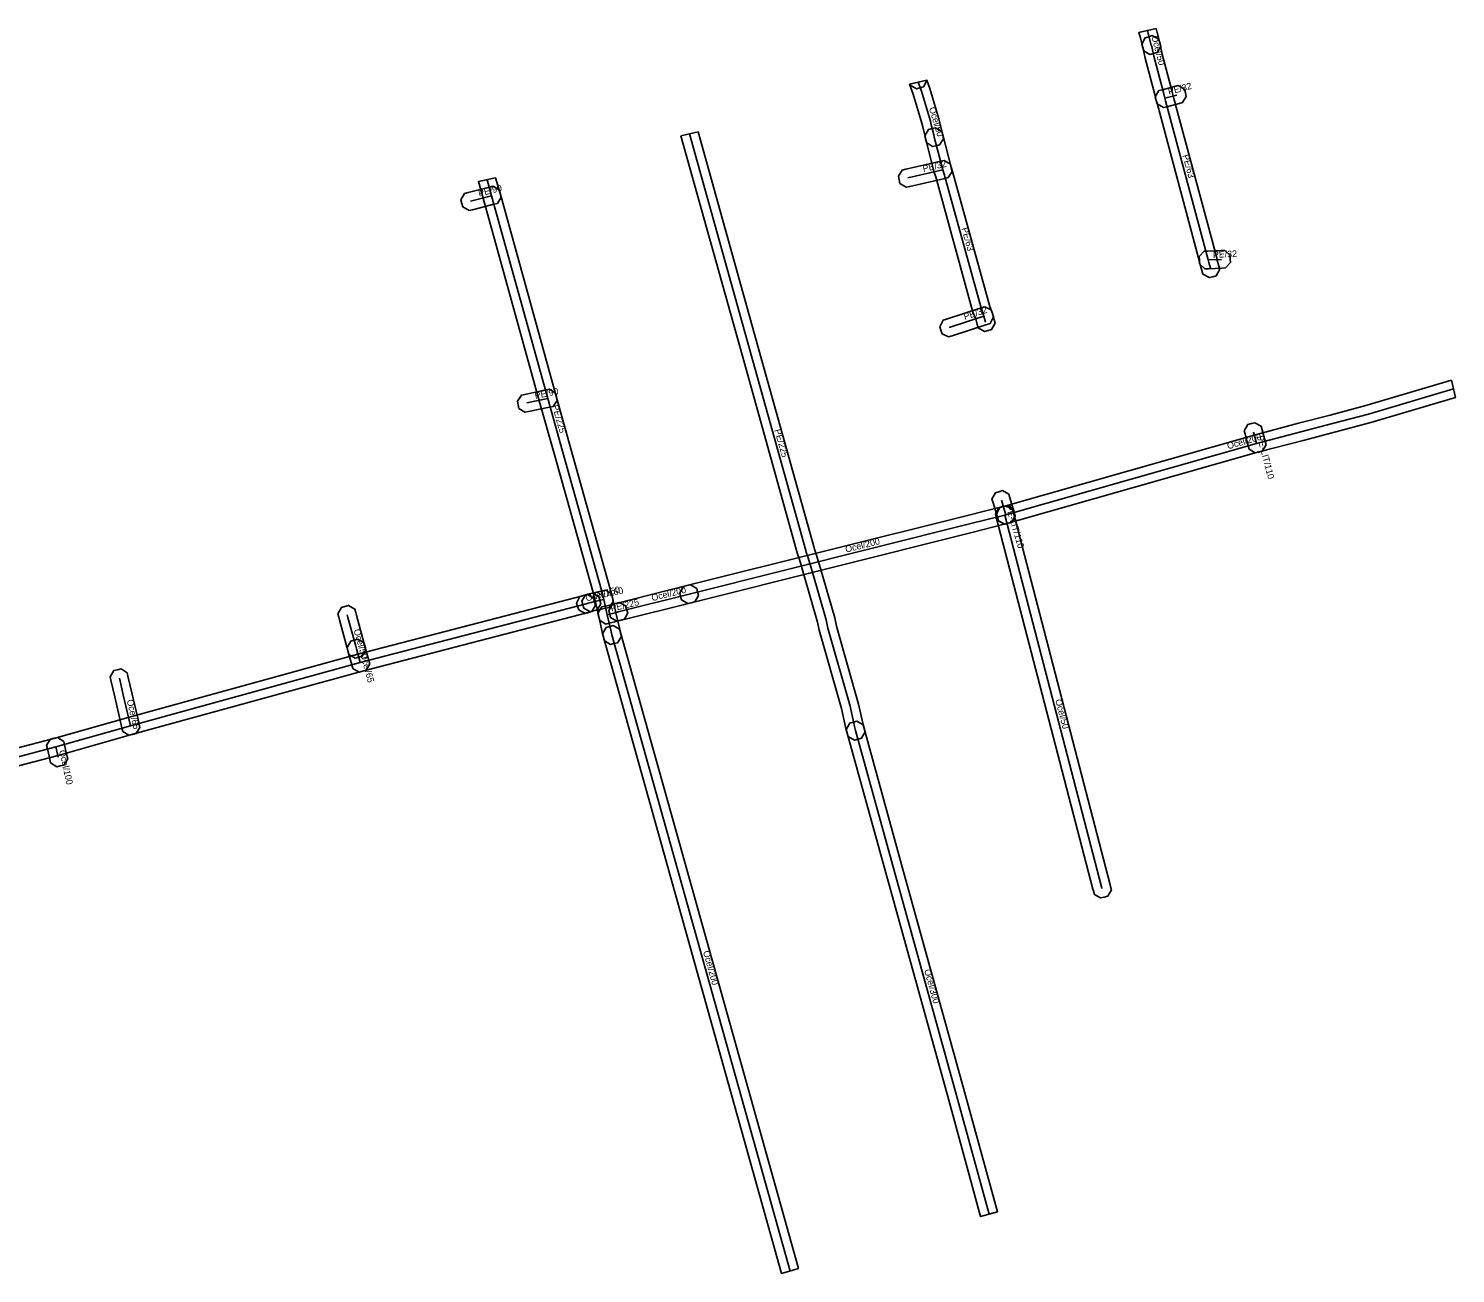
# Model space of a CAD drawing. Extents: x -599265 to -598944, y -1158962 to -1158820.
# Drawn here: x -599106.1 to -598943.9, y -1158961.6 to -1158820.1 of the extents above; entities that cross this region are included whole.
import ezdxf

# ---------------------------------------------------------------- set-up
doc = ezdxf.new("R2010")
doc.units = 0
for name, color, linetype in [('1', 7, 'Continuous'), ('14', 7, 'Continuous'), ('20', 7, 'Continuous'), ('24', 7, 'Continuous'), ('30', 7, 'Continuous')]:
    doc.layers.add(name, color=color, linetype=linetype)

msp = doc.modelspace()

# ---------------------------------------------------------------- linework, layer by layer
at = {"layer": '1'}
for points in [[(-598979.77, -1158821.02), (-598979.92, -1158820.5), (-598977.96, -1158820.06), (-598977.84, -1158820.51), (-598977.53, -1158821.69), (-598977.43, -1158822.09), (-598977.85, -1158822.8), (-598978.25, -1158822.91), (-598978.65, -1158823.01), (-598979.36, -1158822.59), (-598979.47, -1158822.19)], [(-598977.67, -1158821.25), (-598977.54, -1158821.65), (-598977.48, -1158821.86), (-598977.26, -1158822.98), (-598976.15, -1158827.11), (-598976.01, -1158827.73), (-598975.93, -1158828.01), (-598971.07, -1158846.13), (-598971.01, -1158846.42), (-598970.83, -1158847.05), (-598970.72, -1158847.44), (-598971.12, -1158848.17), (-598971.52, -1158848.28), (-598971.92, -1158848.39), (-598972.64, -1158847.99), (-598972.75, -1158847.59), (-598972.95, -1158846.9), (-598973.01, -1158846.6), (-598977.85, -1158828.55), (-598977.95, -1158828.24), (-598978.09, -1158827.58), (-598979.21, -1158823.43), (-598979.42, -1158822.35), (-598979.45, -1158822.24), (-598979.58, -1158821.84), (-598979.19, -1158821.11), (-598978.8, -1158820.99), (-598978.4, -1158820.86)], [(-599005.97, -1158826.4), (-599005.97, -1158826.39), (-599004.01, -1158825.95), (-599003.67, -1158826.89), (-599002.64, -1158830.33), (-599002.54, -1158830.79), (-599002.27, -1158831.9), (-599002.2, -1158832.2), (-599002.12, -1158832.61), (-599002.57, -1158833.3), (-599002.97, -1158833.39), (-599003.38, -1158833.47), (-599004.07, -1158833.02), (-599004.16, -1158832.62), (-599004.21, -1158832.35), (-599004.49, -1158831.24), (-599004.58, -1158830.83), (-599005.57, -1158827.51)], [(-599005.92, -1158826.5), (-599005.95, -1158826.39), (-599004, -1158825.94), (-599004, -1158825.96), (-599004.4, -1158826.68), (-599004.8, -1158826.8), (-599005.2, -1158826.91)], [(-598977.64, -1158827.12), (-598977.23, -1158827.02), (-598975.85, -1158826.65), (-598975.45, -1158826.55), (-598974.73, -1158826.96), (-598974.63, -1158827.36), (-598974.53, -1158827.77), (-598974.94, -1158828.48), (-598975.34, -1158828.59), (-598976.73, -1158828.95), (-598977.13, -1158829.05), (-598977.84, -1158828.64), (-598977.95, -1158828.24), (-598978.05, -1158827.84)], [(-599031.97, -1158832.27), (-599030.02, -1158831.82), (-599022.84, -1158857.56), (-599016.83, -1158879.12), (-599016.78, -1158879.28), (-599016.6, -1158879.85), (-599016.1, -1158881.47), (-599014.49, -1158887.07), (-599014.3, -1158888.01), (-599011.78, -1158896.89), (-599011.27, -1158899.19), (-599011.15, -1158899.63), (-599011.04, -1158900.03), (-599011.44, -1158900.75), (-599011.84, -1158900.86), (-599012.24, -1158900.97), (-599012.96, -1158900.57), (-599013.07, -1158900.17), (-599013.21, -1158899.67), (-599013.72, -1158897.38), (-599016.24, -1158888.49), (-599016.43, -1158887.55), (-599018.02, -1158882.05), (-599018.51, -1158880.45), (-599018.68, -1158879.9), (-599018.75, -1158879.7), (-599024.76, -1158858.1)], [(-599002.32, -1158831.76), (-599002.21, -1158832.16), (-599001.26, -1158835.83), (-599001.09, -1158836.3), (-598996.87, -1158851.67), (-598996.57, -1158852.45), (-598996.36, -1158853.17), (-598996.25, -1158853.57), (-598996.66, -1158854.29), (-598997.06, -1158854.41), (-598997.45, -1158854.52), (-598998.18, -1158854.11), (-598998.29, -1158853.71), (-598998.46, -1158853.09), (-598998.77, -1158852.3), (-599002.99, -1158836.91), (-599003.17, -1158836.43), (-599004.15, -1158832.66), (-599004.25, -1158832.26), (-599003.83, -1158831.54), (-599003.43, -1158831.44), (-599003.03, -1158831.34)], [(-599001.59, -1158837.01), (-599001.99, -1158837.1), (-599005.96, -1158838.01), (-599006.36, -1158838.11), (-599007.07, -1158837.67), (-599007.16, -1158837.26), (-599007.25, -1158836.86), (-599006.81, -1158836.16), (-599006.41, -1158836.06), (-599002.44, -1158835.15), (-599002.03, -1158835.06), (-599001.33, -1158835.5), (-599001.24, -1158835.91), (-599001.15, -1158836.31)], [(-599054.45, -1158839.34), (-599054.99, -1158837.47), (-599053.04, -1158837.03), (-599052.53, -1158838.8), (-599046.15, -1158861.87), (-599044.47, -1158867.86), (-599040.04, -1158883.68), (-599039.75, -1158884.76), (-599039.36, -1158886.5), (-599038.93, -1158888.39), (-599038.83, -1158888.8), (-599038.74, -1158889.2), (-599039.18, -1158889.9), (-599039.59, -1158890), (-599039.99, -1158890.09), (-599040.69, -1158889.65), (-599040.79, -1158889.24), (-599040.88, -1158888.84), (-599041.32, -1158886.94), (-599041.69, -1158885.24), (-599041.96, -1158884.2), (-599046.39, -1158868.4), (-599048.07, -1158862.41)], [(-599052.84, -1158839.94), (-599053.24, -1158840.04), (-599055.66, -1158840.66), (-599056.06, -1158840.76), (-599056.78, -1158840.34), (-599056.88, -1158839.94), (-599056.98, -1158839.54), (-599056.56, -1158838.82), (-599056.16, -1158838.72), (-599053.74, -1158838.1), (-599053.34, -1158838), (-599052.62, -1158838.42), (-599052.52, -1158838.82), (-599052.42, -1158839.22)], [(-598972.49, -1158845.39), (-598972.08, -1158845.37), (-598970.57, -1158845.31), (-598970.15, -1158845.29), (-598969.55, -1158845.86), (-598969.53, -1158846.27), (-598969.51, -1158846.68), (-598970.08, -1158847.29), (-598970.49, -1158847.31), (-598972, -1158847.37), (-598972.42, -1158847.38), (-598973.02, -1158846.82), (-598973.04, -1158846.41), (-598973.06, -1158845.99)], [(-598996.81, -1158853.59), (-598997.21, -1158853.72), (-599001.15, -1158855.01), (-599001.55, -1158855.13), (-599002.29, -1158854.76), (-599002.41, -1158854.36), (-599002.54, -1158853.97), (-599002.17, -1158853.23), (-599001.77, -1158853.1), (-598997.83, -1158851.82), (-598997.43, -1158851.69), (-598996.69, -1158852.06), (-598996.57, -1158852.46), (-598996.44, -1158852.85)], [(-598944.39, -1158860.06), (-598943.93, -1158862.01), (-598953.56, -1158864.86), (-598957.67, -1158865.95), (-598961.24, -1158866.89), (-598966.27, -1158868.21), (-598994.77, -1158876.32), (-598995.16, -1158876.44), (-598995.89, -1158876.03), (-598996, -1158875.63), (-598996.11, -1158875.24), (-598995.71, -1158874.51), (-598995.31, -1158874.4), (-598966.8, -1158866.29), (-598961.76, -1158864.95), (-598958.18, -1158864.01), (-598954.1, -1158862.94)], [(-599046.5, -1158863.03), (-599046.91, -1158863.12), (-599049.3, -1158863.62), (-599049.7, -1158863.7), (-599050.39, -1158863.25), (-599050.48, -1158862.84), (-599050.56, -1158862.44), (-599050.11, -1158861.75), (-599049.7, -1158861.66), (-599047.32, -1158861.16), (-599046.91, -1158861.08), (-599046.22, -1158861.53), (-599046.13, -1158861.94), (-599046.05, -1158862.34)], [(-598966.01, -1158865.29), (-598965.9, -1158865.69), (-598965.56, -1158867), (-598965.46, -1158867.4), (-598965.88, -1158868.11), (-598966.28, -1158868.22), (-598966.68, -1158868.32), (-598967.39, -1158867.9), (-598967.5, -1158867.5), (-598967.84, -1158866.2), (-598967.94, -1158865.8), (-598967.53, -1158865.08), (-598967.12, -1158864.98), (-598966.72, -1158864.88)], [(-598994.69, -1158873.01), (-598994.58, -1158873.41), (-598994.08, -1158875.08), (-598993.96, -1158875.47), (-598994.36, -1158876.2), (-598994.76, -1158876.32), (-598995.15, -1158876.44), (-598995.88, -1158876.04), (-598996, -1158875.64), (-598996.49, -1158873.98), (-598996.61, -1158873.58), (-598996.22, -1158872.85), (-598995.82, -1158872.73), (-598995.42, -1158872.61)], [(-599031.69, -1158883.51), (-599031.29, -1158883.41), (-598999.4, -1158875.43), (-598995.52, -1158874.45), (-598995.39, -1158874.42), (-598995.3, -1158874.4), (-598994.9, -1158874.29), (-598994.18, -1158874.7), (-598994.08, -1158875.1), (-598993.97, -1158875.5), (-598994.38, -1158876.22), (-598994.78, -1158876.32), (-598994.91, -1158876.36), (-598995.06, -1158876.39), (-598998.92, -1158877.37), (-599030.8, -1158885.35), (-599031.2, -1158885.45), (-599031.91, -1158885.03), (-599032.01, -1158884.63), (-599032.11, -1158884.22)], [(-598994.29, -1158874.74), (-598994.18, -1158875.14), (-598983.19, -1158917.42), (-598983.14, -1158917.61), (-598983.04, -1158918.01), (-598983.45, -1158918.72), (-598983.86, -1158918.83), (-598984.26, -1158918.93), (-598984.97, -1158918.52), (-598985.08, -1158918.11), (-598985.13, -1158917.92), (-598996.12, -1158875.64), (-598996.22, -1158875.24), (-598995.8, -1158874.53), (-598995.4, -1158874.42), (-598995, -1158874.32)], [(-599041.5, -1158886.18), (-599041.9, -1158886.29), (-599042.22, -1158886.37), (-599042.47, -1158886.45), (-599042.86, -1158886.57), (-599043.59, -1158886.18), (-599043.72, -1158885.78), (-599043.84, -1158885.39), (-599043.45, -1158884.66), (-599043.05, -1158884.53), (-599042.78, -1158884.45), (-599042.42, -1158884.35), (-599042.02, -1158884.25), (-599041.3, -1158884.66), (-599041.19, -1158885.06), (-599041.09, -1158885.47)], [(-599040.11, -1158885.9), (-599040.52, -1158885.98), (-599041.56, -1158886.19), (-599041.9, -1158886.28), (-599042.3, -1158886.39), (-599043.02, -1158885.98), (-599043.12, -1158885.58), (-599043.23, -1158885.18), (-599042.82, -1158884.46), (-599042.42, -1158884.35), (-599042.02, -1158884.25), (-599040.92, -1158884.02), (-599040.52, -1158883.94), (-599039.82, -1158884.39), (-599039.74, -1158884.8), (-599039.66, -1158885.21)], [(-599039.74, -1158885.53), (-599039.34, -1158885.43), (-599031.29, -1158883.41), (-599030.89, -1158883.31), (-599030.18, -1158883.74), (-599030.07, -1158884.14), (-599029.97, -1158884.54), (-599030.4, -1158885.25), (-599030.8, -1158885.35), (-599038.86, -1158887.37), (-599039.26, -1158887.47), (-599039.97, -1158887.04), (-599040.07, -1158886.64), (-599040.17, -1158886.24)], [(-599069.71, -1158891.24), (-599069.82, -1158890.84), (-599069.9, -1158890.54), (-599070.79, -1158887.3), (-599070.87, -1158887), (-599070.97, -1158886.6), (-599070.56, -1158885.88), (-599070.16, -1158885.77), (-599069.76, -1158885.67), (-599069.04, -1158886.08), (-599068.93, -1158886.48), (-599068.85, -1158886.78), (-599067.96, -1158890.02), (-599067.88, -1158890.32), (-599067.78, -1158890.72), (-599068.19, -1158891.44), (-599068.59, -1158891.55), (-599068.99, -1158891.65)], [(-599040.97, -1158885.84), (-599040.57, -1158885.75), (-599039.71, -1158885.55), (-599039.41, -1158885.45), (-599039.01, -1158885.32), (-599038.28, -1158885.7), (-599038.15, -1158886.09), (-599038.02, -1158886.49), (-599038.4, -1158887.22), (-599038.79, -1158887.35), (-599039.17, -1158887.47), (-599040.11, -1158887.69), (-599040.52, -1158887.79), (-599041.22, -1158887.35), (-599041.31, -1158886.95), (-599041.41, -1158886.54)], [(-599018.6, -1158961.08), (-599020.53, -1158961.63), (-599040.77, -1158889.29), (-599040.89, -1158888.89), (-599040.48, -1158888.17), (-599040.08, -1158888.06), (-599039.68, -1158887.95), (-599038.96, -1158888.35), (-599038.85, -1158888.75)], [(-599069.28, -1158892.83), (-599069.39, -1158892.43), (-599069.82, -1158890.84), (-599069.92, -1158890.44), (-599069.51, -1158889.72), (-599069.11, -1158889.61), (-599068.71, -1158889.51), (-599067.99, -1158889.92), (-599067.89, -1158890.32), (-599067.45, -1158891.91), (-599067.35, -1158892.31), (-599067.76, -1158893.03), (-599068.16, -1158893.14), (-599068.56, -1158893.24)], [(-599095.42, -1158899.99), (-599095.51, -1158899.59), (-599096.33, -1158896.06), (-599096.77, -1158894.18), (-599096.87, -1158893.78), (-599096.43, -1158893.07), (-599096.03, -1158892.98), (-599095.62, -1158892.88), (-599094.92, -1158893.32), (-599094.83, -1158893.72), (-599094.39, -1158895.6), (-599093.57, -1158899.13), (-599093.47, -1158899.54), (-599093.91, -1158900.24), (-599094.31, -1158900.33), (-599094.72, -1158900.43)], [(-598999.72, -1158940.98), (-598995.99, -1158954.61), (-598997.91, -1158955.16), (-599001.64, -1158941.51), (-599008.69, -1158916.08), (-599013.07, -1158900.17), (-599013.18, -1158899.77), (-599012.78, -1158899.05), (-599012.38, -1158898.94), (-599011.98, -1158898.83), (-599011.26, -1158899.24), (-599011.15, -1158899.64), (-599006.77, -1158915.54)], [(-599102.12, -1158901.13), (-599102.03, -1158901.53), (-599101.77, -1158902.71), (-599101.68, -1158903.12), (-599102.12, -1158903.82), (-599102.53, -1158903.91), (-599102.93, -1158904), (-599103.63, -1158903.55), (-599103.72, -1158903.15), (-599103.99, -1158901.97), (-599104.08, -1158901.56), (-599103.63, -1158900.86), (-599103.23, -1158900.77), (-599102.82, -1158900.68)]]:
    msp.add_lwpolyline(points, close=True, dxfattribs=at)
msp.add_lwpolyline([(-599109.54, -1158902.43), (-599103.27, -1158900.78), (-599094.81, -1158898.4), (-599068.68, -1158891.2), (-599043.01, -1158884.52), (-599042.61, -1158884.42), (-599041.9, -1158884.84), (-599041.79, -1158885.24), (-599041.69, -1158885.64), (-599042.11, -1158886.35), (-599042.51, -1158886.46), (-599068.16, -1158893.14), (-599094.27, -1158900.32), (-599102.75, -1158902.72), (-599109.03, -1158904.37)], dxfattribs=at)
at = {"layer": '14'}
for points in [[(-599054.01, -1158837.25), (-599053.49, -1158839.07), (-599047.11, -1158862.14), (-599045.43, -1158868.13), (-599041, -1158883.94), (-599040.72, -1158885), (-599040.34, -1158886.72), (-599039.9, -1158888.61), (-599039.81, -1158889.02)], [(-599053.49, -1158839.07), (-599055.91, -1158839.69)], [(-598995.04, -1158875.36), (-598966.53, -1158867.25), (-598961.5, -1158865.92), (-598957.92, -1158864.98), (-598953.83, -1158863.9), (-598944.16, -1158861.03)], [(-599047.11, -1158862.14), (-599049.5, -1158862.64)], [(-598966.87, -1158865.95), (-598966.53, -1158867.25)], [(-598995.54, -1158873.69), (-598995.04, -1158875.36)], [(-599031.04, -1158884.38), (-598999.16, -1158876.4), (-598995.29, -1158875.42), (-598995.15, -1158875.39), (-598995.04, -1158875.36)], [(-598995.15, -1158875.39), (-598984.16, -1158917.67), (-598984.11, -1158917.86)], [(-599039.1, -1158886.4), (-599031.04, -1158884.38)], [(-599042.76, -1158885.49), (-599068.42, -1158892.17), (-599094.54, -1158899.36), (-599103.01, -1158901.75), (-599109.28, -1158903.4), (-599121.29, -1158906.57), (-599128.03, -1158908.44), (-599139.52, -1158911.69), (-599140.38, -1158911.93), (-599166.16, -1158919.18), (-599194.33, -1158927.1), (-599199.24, -1158928.46), (-599225.65, -1158935.9)], [(-599042.16, -1158885.32), (-599042.5, -1158885.41), (-599042.76, -1158885.49)], [(-599040.72, -1158885), (-599041.79, -1158885.22), (-599042.16, -1158885.32)], [(-599068.85, -1158890.58), (-599068.93, -1158890.28), (-599069.82, -1158887.04), (-599069.9, -1158886.74)], [(-599040.34, -1158886.72), (-599039.44, -1158886.51), (-599039.1, -1158886.4)], [(-599039.81, -1158889.02), (-599019.56, -1158961.35)], [(-599068.42, -1158892.17), (-599068.85, -1158890.58)], [(-599094.54, -1158899.36), (-599095.36, -1158895.83), (-599095.8, -1158893.95)], [(-599103.01, -1158901.75), (-599102.75, -1158902.93)]]:
    msp.add_lwpolyline(points, dxfattribs=at)
at = {"layer": '24'}
for points in [[(-598978.94, -1158820.28), (-598978.81, -1158820.76), (-598978.5, -1158821.94)], [(-598978.5, -1158821.94), (-598978.45, -1158822.11), (-598978.23, -1158823.21), (-598977.12, -1158827.34), (-598976.98, -1158827.98), (-598976.89, -1158828.28), (-598972.04, -1158846.37), (-598971.98, -1158846.66), (-598971.79, -1158847.32)], [(-599004.99, -1158826.17), (-599004.62, -1158827.2), (-599003.61, -1158830.58), (-599003.52, -1158831.02), (-599003.24, -1158832.13), (-599003.18, -1158832.41)], [(-598976.98, -1158827.98), (-598975.6, -1158827.62)], [(-599012.11, -1158899.9), (-599012.24, -1158899.43), (-599012.75, -1158897.13), (-599015.27, -1158888.25), (-599015.46, -1158887.31), (-599017.06, -1158881.76), (-599017.56, -1158880.15), (-599017.73, -1158879.59), (-599017.79, -1158879.41), (-599023.8, -1158857.83), (-599030.99, -1158832.05)], [(-599003.18, -1158832.41), (-599002.21, -1158836.13), (-599002.04, -1158836.61), (-598997.82, -1158851.98), (-598997.52, -1158852.77), (-598997.33, -1158853.44)], [(-599002.21, -1158836.13), (-599006.18, -1158837.04)], [(-598972.04, -1158846.37), (-598970.53, -1158846.31)], [(-598997.52, -1158852.77), (-599001.46, -1158854.05)], [(-598996.95, -1158954.89), (-599000.68, -1158941.24), (-599007.73, -1158915.81), (-599012.11, -1158899.9)]]:
    msp.add_lwpolyline(points, dxfattribs=at)

# ---------------------------------------------------------------- texts
at = {"layer": '20'}
for s, rotation, p in [('PE/90', 14.37, (-599054.9, -1158839.18)), ('PE/90', 11.8161, (-599048.51, -1158862.19)), ('PE/225', 285.6671, (-599046.62, -1158862.96)), ('Ocel/200', 15.879, (-598969.77, -1158867.91)), ('PE-LIT/110', 284.6656, (-598966.49, -1158866.45)), ('PE-LIT/110', 286.5196, (-598995.07, -1158874.37)), ('Ocel/200', 14.0565, (-599013.19, -1158879.66)), ('Ocel/150', 14.8265, (-599042.71, -1158885.21)), ('PE/160', 11.6185, (-599041.69, -1158884.96)), ('Ocel/200', 14.0563, (-599035.22, -1158885.18)), ('PE/225', 13.134, (-599039.87, -1158886.36)), ('Ocel/50', 285.3598, (-599069.18, -1158888.46)), ('Ocel/65', 285.1331, (-599068.44, -1158891.18)), ('Ocel/65', 283.0776, (-599094.97, -1158896.45)), ('Ocel/50', 284.5707, (-598989.43, -1158896.43)), ('Ocel/100', 282.6007, (-599102.67, -1158902.19)), ('Ocel/200', 285.6366, (-599029.47, -1158925.04))]:
    msp.add_text(s, height=0.75, rotation=rotation, dxfattribs=at).set_placement(p)
at = {"layer": '30'}
for s, rotation, p in [('Ocel/50', 284.607, (-598978.5, -1158820.96)), ('PE/32', 14.7354, (-598976.49, -1158827.6)), ('Ocel/50', 286.6884, (-599003.79, -1158829.11)), ('PE/63', 285.0136, (-598974.97, -1158834.49)), ('PE/32', 12.9134, (-599004.4, -1158836.38)), ('PE/63', 285.3393, (-599000.09, -1158842.79)), ('PE/32', 2.2361, (-598971.48, -1158846.14)), ('PE/32', 18.0376, (-598999.69, -1158853.21)), ('PE/225', 285.5624, (-599021.35, -1158865.72)), ('Ocel/300', 285.4951, (-599004.33, -1158927.14))]:
    msp.add_text(s, height=0.75, rotation=rotation, dxfattribs=at).set_placement(p)

doc.saveas('drawing.dxf')
